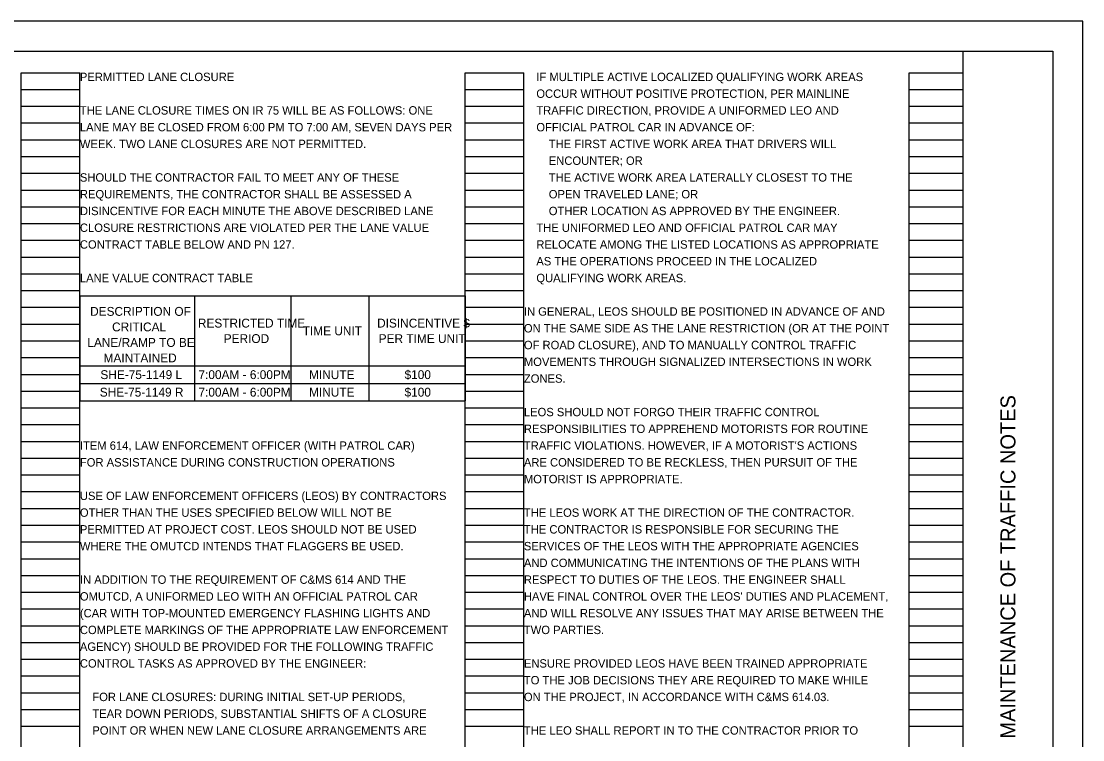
# Model space of a CAD drawing. Extents: x 0 to 34, y 0 to 22.
# Drawn here: x 16.26 to 34, y 9.99 to 22 of the extents above; entities that cross this region are included whole.
import ezdxf

# ---------------------------------------------------------------- set-up
doc = ezdxf.new("R2010")
doc.units = 0
for name, color, linetype in [('Default', 7, 'Continuous'), ('SH_Border', 7, 'Continuous'), ('SH_Cut_Line', 7, 'Continuous'), ('SH_Data', 7, 'Continuous'), ('SH_Text', 7, 'Continuous')]:
    doc.layers.add(name, color=color, linetype=linetype)

msp = doc.modelspace()

# ---------------------------------------------------------------- linework, layer by layer
at = {"layer": 'Default'}
for p, q in [((17.24, 17.412), (23.68, 17.412)), ((17.24, 17.412), (17.24, 15.656)), ((19.157, 17.412), (19.157, 15.656)), ((20.768, 17.412), (20.768, 15.656)), ((22.07, 17.412), (22.07, 15.656)), ((23.68, 17.412), (23.68, 15.656)), ((17.24, 16.241), (23.68, 16.241)), ((17.24, 15.949), (23.68, 15.949)), ((17.24, 15.656), (23.68, 15.656))]:
    msp.add_line(p, q, dxfattribs=at)
at = {"layer": 'SH_Border'}
msp.add_line((32, 0.5), (32, 21.5), dxfattribs=at)
msp.add_lwpolyline([(1.5, 21.5), (33.5, 21.5), (33.5, 0.5), (1.5, 0.5)], close=True, dxfattribs=at)
at = {"layer": 'SH_Cut_Line'}
msp.add_lwpolyline([(0, 0), (34, 0), (34, 22), (0, 22)], close=True, dxfattribs=at)
at = {"layer": 'SH_Data'}
for p, q in [((16.26, 0.98), (16.26, 21.14)), ((16.26, 21.14), (17.24, 21.14)), ((17.24, 0.98), (17.24, 21.14)), ((23.68, 0.98), (23.68, 21.14)), ((23.68, 21.14), (24.66, 21.14)), ((24.66, 0.98), (24.66, 21.14)), ((31.1, 0.98), (31.1, 21.14)), ((31.1, 21.14), (32, 21.14)), ((32, 0.98), (32, 21.14)), ((16.26, 20.86), (17.24, 20.86)), ((23.68, 20.86), (24.66, 20.86)), ((31.1, 20.86), (32, 20.86)), ((16.26, 20.58), (17.24, 20.58)), ((23.68, 20.58), (24.66, 20.58)), ((31.1, 20.58), (32, 20.58)), ((16.26, 20.3), (17.24, 20.3)), ((23.68, 20.3), (24.66, 20.3)), ((31.1, 20.3), (32, 20.3)), ((16.26, 20.02), (17.24, 20.02)), ((23.68, 20.02), (24.66, 20.02)), ((31.1, 20.02), (32, 20.02)), ((16.26, 19.74), (17.24, 19.74)), ((23.68, 19.74), (24.66, 19.74)), ((31.1, 19.74), (32, 19.74)), ((16.26, 19.46), (17.24, 19.46)), ((23.68, 19.46), (24.66, 19.46)), ((31.1, 19.46), (32, 19.46)), ((16.26, 19.18), (17.24, 19.18)), ((23.68, 19.18), (24.66, 19.18)), ((31.1, 19.18), (32, 19.18)), ((16.26, 18.9), (17.24, 18.9)), ((23.68, 18.9), (24.66, 18.9)), ((31.1, 18.9), (32, 18.9)), ((16.26, 18.62), (17.24, 18.62)), ((23.68, 18.62), (24.66, 18.62)), ((31.1, 18.62), (32, 18.62)), ((16.26, 18.34), (17.24, 18.34)), ((23.68, 18.34), (24.66, 18.34)), ((31.1, 18.34), (32, 18.34)), ((16.26, 18.06), (17.24, 18.06)), ((23.68, 18.06), (24.66, 18.06)), ((31.1, 18.06), (32, 18.06)), ((16.26, 17.78), (17.24, 17.78)), ((23.68, 17.78), (24.66, 17.78)), ((31.1, 17.78), (32, 17.78)), ((16.26, 17.5), (17.24, 17.5)), ((23.68, 17.5), (24.66, 17.5)), ((31.1, 17.5), (32, 17.5)), ((16.26, 17.22), (17.24, 17.22)), ((23.68, 17.22), (24.66, 17.22)), ((31.1, 17.22), (32, 17.22)), ((16.26, 16.94), (17.24, 16.94)), ((23.68, 16.94), (24.66, 16.94)), ((31.1, 16.94), (32, 16.94)), ((16.26, 16.66), (17.24, 16.66)), ((23.68, 16.66), (24.66, 16.66)), ((31.1, 16.66), (32, 16.66)), ((16.26, 16.38), (17.24, 16.38)), ((23.68, 16.38), (24.66, 16.38)), ((31.1, 16.38), (32, 16.38)), ((16.26, 16.1), (17.24, 16.1)), ((23.68, 16.1), (24.66, 16.1)), ((31.1, 16.1), (32, 16.1)), ((16.26, 15.82), (17.24, 15.82)), ((23.68, 15.82), (24.66, 15.82)), ((31.1, 15.82), (32, 15.82)), ((16.26, 15.54), (17.24, 15.54)), ((23.68, 15.54), (24.66, 15.54)), ((31.1, 15.54), (32, 15.54)), ((16.26, 15.26), (17.24, 15.26)), ((23.68, 15.26), (24.66, 15.26)), ((31.1, 15.26), (32, 15.26)), ((16.26, 14.98), (17.24, 14.98)), ((23.68, 14.98), (24.66, 14.98)), ((31.1, 14.98), (32, 14.98)), ((16.26, 14.7), (17.24, 14.7)), ((23.68, 14.7), (24.66, 14.7)), ((31.1, 14.7), (32, 14.7)), ((16.26, 14.42), (17.24, 14.42)), ((23.68, 14.42), (24.66, 14.42)), ((31.1, 14.42), (32, 14.42)), ((16.26, 14.14), (17.24, 14.14)), ((23.68, 14.14), (24.66, 14.14)), ((31.1, 14.14), (32, 14.14)), ((16.26, 13.86), (17.24, 13.86)), ((23.68, 13.86), (24.66, 13.86)), ((31.1, 13.86), (32, 13.86)), ((16.26, 13.58), (17.24, 13.58)), ((23.68, 13.58), (24.66, 13.58)), ((31.1, 13.58), (32, 13.58)), ((16.26, 13.3), (17.24, 13.3)), ((23.68, 13.3), (24.66, 13.3)), ((31.1, 13.3), (32, 13.3)), ((16.26, 13.02), (17.24, 13.02)), ((23.68, 13.02), (24.66, 13.02)), ((31.1, 13.02), (32, 13.02)), ((16.26, 12.74), (17.24, 12.74)), ((23.68, 12.74), (24.66, 12.74)), ((31.1, 12.74), (32, 12.74)), ((16.26, 12.46), (17.24, 12.46)), ((23.68, 12.46), (24.66, 12.46)), ((31.1, 12.46), (32, 12.46)), ((16.26, 12.18), (17.24, 12.18)), ((23.68, 12.18), (24.66, 12.18)), ((31.1, 12.18), (32, 12.18)), ((16.26, 11.9), (17.24, 11.9)), ((23.68, 11.9), (24.66, 11.9)), ((31.1, 11.9), (32, 11.9)), ((16.26, 11.62), (17.24, 11.62)), ((23.68, 11.62), (24.66, 11.62)), ((31.1, 11.62), (32, 11.62)), ((16.26, 11.34), (17.24, 11.34)), ((23.68, 11.34), (24.66, 11.34)), ((31.1, 11.34), (32, 11.34)), ((16.26, 11.06), (17.24, 11.06)), ((23.68, 11.06), (24.66, 11.06)), ((31.1, 11.06), (32, 11.06)), ((16.26, 10.78), (17.24, 10.78)), ((23.68, 10.78), (24.66, 10.78)), ((31.1, 10.78), (32, 10.78)), ((16.26, 10.5), (17.24, 10.5)), ((23.68, 10.5), (24.66, 10.5)), ((31.1, 10.5), (32, 10.5)), ((16.26, 10.22), (17.24, 10.22)), ((23.68, 10.22), (24.66, 10.22)), ((31.1, 10.22), (32, 10.22))]:
    msp.add_line(p, q, dxfattribs=at)

# ---------------------------------------------------------------- texts
at = {"layer": 'Default'}
for s, height, p in [('DESCRIPTION OF', 0.14813, (17.411, 17.078)), ('RESTRICTED TIME ', 0.14813, (19.212, 16.882)), ('DISINCENTIVE $', 0.14813, (22.207, 16.882)), ('CRITICAL', 0.1481, (17.778, 16.818)), ('TIME UNIT', 0.1481, (20.964, 16.753)), ('LANE/RAMP TO BE', 0.14813, (17.365, 16.559)), ('PERIOD', 0.1481, (19.644, 16.623)), ('PER TIME UNIT', 0.14813, (22.234, 16.623)), ('MAINTAINED', 0.1481, (17.636, 16.3)), ('SHE-75-1149 L', 0.14813, (17.583, 16.021)), ('7:00AM - 6:00PM', 0.14813, (19.222, 16.021)), ('MINUTE', 0.1481, (21.07, 16.021)), ('$100', 0.1481, (22.666, 16.021)), ('SHE-75-1149 R', 0.14813, (17.573, 15.728)), ('7:00AM - 6:00PM', 0.14813, (19.222, 15.728)), ('MINUTE', 0.1481, (21.07, 15.728)), ('$100', 0.1481, (22.666, 15.728))]:
    msp.add_text(s, height=height, dxfattribs=at).set_placement(p)
at = {"layer": 'SH_Data'}
msp.add_text('MAINTENANCE OF TRAFFIC NOTES', height=0.25, rotation=90, dxfattribs=at).set_placement((32.875, 10.014))
at = {"layer": 'SH_Text'}
for s, p in [('PERMITTED LANE CLOSURE', (17.24, 21)), ('    IF MULTIPLE ACTIVE LOCALIZED QUALIFYING WORK AREAS', (24.66, 21)), ('    OCCUR WITHOUT POSITIVE PROTECTION, PER MAINLINE', (24.66, 20.72)), ('THE LANE CLOSURE TIMES ON IR 75 WILL BE AS FOLLOWS: ONE', (17.24, 20.44)), ('    TRAFFIC DIRECTION, PROVIDE A UNIFORMED LEO AND', (24.66, 20.44)), ('LANE MAY BE CLOSED FROM 6:00 PM TO 7:00 AM, SEVEN DAYS PER', (17.24, 20.16)), ('    OFFICIAL PATROL CAR IN ADVANCE OF:', (24.66, 20.16)), ('WEEK. TWO LANE CLOSURES ARE NOT PERMITTED.', (17.24, 19.88)), ('        THE FIRST ACTIVE WORK AREA THAT DRIVERS WILL', (24.66, 19.88)), ('        ENCOUNTER; OR', (24.66, 19.6)), ('SHOULD THE CONTRACTOR FAIL TO MEET ANY OF THESE', (17.24, 19.32)), ('        THE ACTIVE WORK AREA LATERALLY CLOSEST TO THE', (24.66, 19.32)), ('REQUIREMENTS, THE CONTRACTOR SHALL BE ASSESSED A', (17.24, 19.04)), ('        OPEN TRAVELED LANE; OR', (24.66, 19.04)), ('DISINCENTIVE FOR EACH MINUTE THE ABOVE DESCRIBED LANE', (17.24, 18.76)), ('        OTHER LOCATION AS APPROVED BY THE ENGINEER.', (24.66, 18.76)), ('CLOSURE RESTRICTIONS ARE VIOLATED PER THE LANE VALUE', (17.24, 18.48)), ('    THE UNIFORMED LEO AND OFFICIAL PATROL CAR MAY', (24.66, 18.48)), ('CONTRACT TABLE BELOW AND PN 127.', (17.24, 18.2)), ('    RELOCATE AMONG THE LISTED LOCATIONS AS APPROPRIATE', (24.66, 18.2)), ('    AS THE OPERATIONS PROCEED IN THE LOCALIZED', (24.66, 17.92)), ('LANE VALUE CONTRACT TABLE', (17.24, 17.64)), ('    QUALIFYING WORK AREAS.', (24.66, 17.64)), ('IN GENERAL, LEOS SHOULD BE POSITIONED IN ADVANCE OF AND', (24.66, 17.08)), ('ON THE SAME SIDE AS THE LANE RESTRICTION (OR AT THE POINT', (24.66, 16.8)), ('OF ROAD CLOSURE), AND TO MANUALLY CONTROL TRAFFIC', (24.66, 16.52)), ('MOVEMENTS THROUGH SIGNALIZED INTERSECTIONS IN WORK', (24.66, 16.24)), ('ZONES.', (24.66, 15.96)), ('LEOS SHOULD NOT FORGO THEIR TRAFFIC CONTROL', (24.66, 15.4)), ('RESPONSIBILITIES TO APPREHEND MOTORISTS FOR ROUTINE', (24.66, 15.12)), ('ITEM 614, LAW ENFORCEMENT OFFICER (WITH PATROL CAR)', (17.24, 14.84)), ("TRAFFIC VIOLATIONS. HOWEVER, IF A MOTORIST'S ACTIONS", (24.66, 14.84)), ('FOR ASSISTANCE DURING CONSTRUCTION OPERATIONS', (17.24, 14.56)), ('ARE CONSIDERED TO BE RECKLESS, THEN PURSUIT OF THE', (24.66, 14.56)), ('MOTORIST IS APPROPRIATE.', (24.66, 14.28)), ('USE OF LAW ENFORCEMENT OFFICERS (LEOS) BY CONTRACTORS', (17.24, 14)), ('OTHER THAN THE USES SPECIFIED BELOW WILL NOT BE', (17.24, 13.72)), ('THE LEOS WORK AT THE DIRECTION OF THE CONTRACTOR.', (24.66, 13.72)), ('PERMITTED AT PROJECT COST. LEOS SHOULD NOT BE USED', (17.24, 13.44)), ('THE CONTRACTOR IS RESPONSIBLE FOR SECURING THE', (24.66, 13.44)), ('WHERE THE OMUTCD INTENDS THAT FLAGGERS BE USED.', (17.24, 13.16)), ('SERVICES OF THE LEOS WITH THE APPROPRIATE AGENCIES', (24.66, 13.16)), ('AND COMMUNICATING THE INTENTIONS OF THE PLANS WITH', (24.66, 12.88)), ('IN ADDITION TO THE REQUIREMENT OF C&MS 614 AND THE', (17.24, 12.6)), ('RESPECT TO DUTIES OF THE LEOS. THE ENGINEER SHALL', (24.66, 12.6)), ('OMUTCD, A UNIFORMED LEO WITH AN OFFICIAL PATROL CAR', (17.24, 12.32)), ("HAVE FINAL CONTROL OVER THE LEOS' DUTIES AND PLACEMENT,", (24.66, 12.32)), ('(CAR WITH TOP-MOUNTED EMERGENCY FLASHING LIGHTS AND', (17.24, 12.04)), ('AND WILL RESOLVE ANY ISSUES THAT MAY ARISE BETWEEN THE', (24.66, 12.04)), ('COMPLETE MARKINGS OF THE APPROPRIATE LAW ENFORCEMENT', (17.24, 11.76)), ('TWO PARTIES.', (24.66, 11.76)), ('AGENCY) SHOULD BE PROVIDED FOR THE FOLLOWING TRAFFIC', (17.24, 11.48)), ('CONTROL TASKS AS APPROVED BY THE ENGINEER:', (17.24, 11.2)), ('ENSURE PROVIDED LEOS HAVE BEEN TRAINED APPROPRIATE', (24.66, 11.2)), ('TO THE JOB DECISIONS THEY ARE REQUIRED TO MAKE WHILE', (24.66, 10.92)), ('    FOR LANE CLOSURES: DURING INITIAL SET-UP PERIODS,', (17.24, 10.64)), ('ON THE PROJECT, IN ACCORDANCE WITH C&MS 614.03.', (24.66, 10.64)), ('    TEAR DOWN PERIODS, SUBSTANTIAL SHIFTS OF A CLOSURE', (17.24, 10.36)), ('    POINT OR WHEN NEW LANE CLOSURE ARRANGEMENTS ARE', (17.24, 10.08)), ('THE LEO SHALL REPORT IN TO THE CONTRACTOR PRIOR TO', (24.66, 10.08))]:
    msp.add_text(s, height=0.14, dxfattribs=at).set_placement(p)

doc.saveas('drawing.dxf')
